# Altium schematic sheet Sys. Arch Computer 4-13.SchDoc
size 762 x 381 mm; SheetNumber: 1; SheetTotal: 1
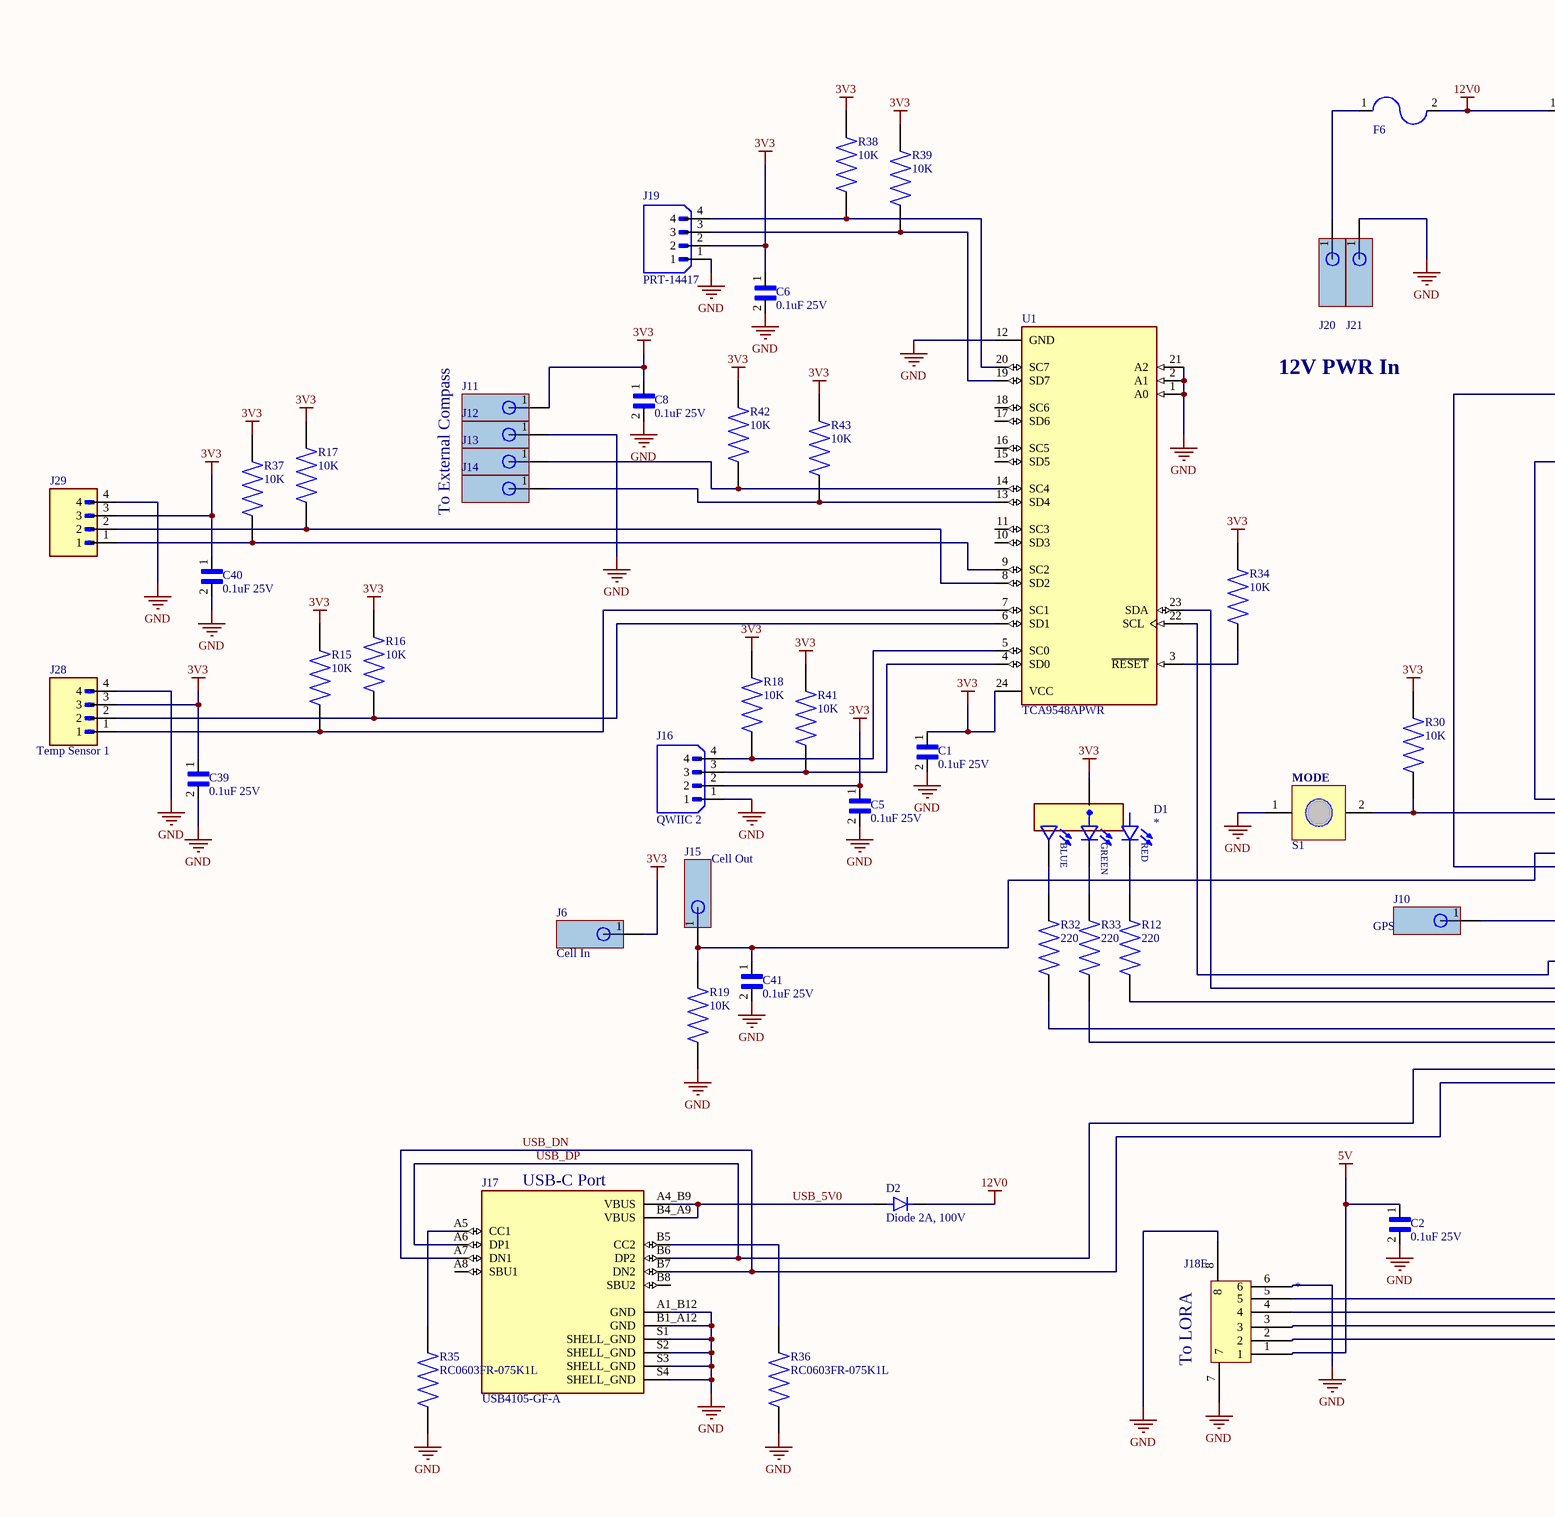
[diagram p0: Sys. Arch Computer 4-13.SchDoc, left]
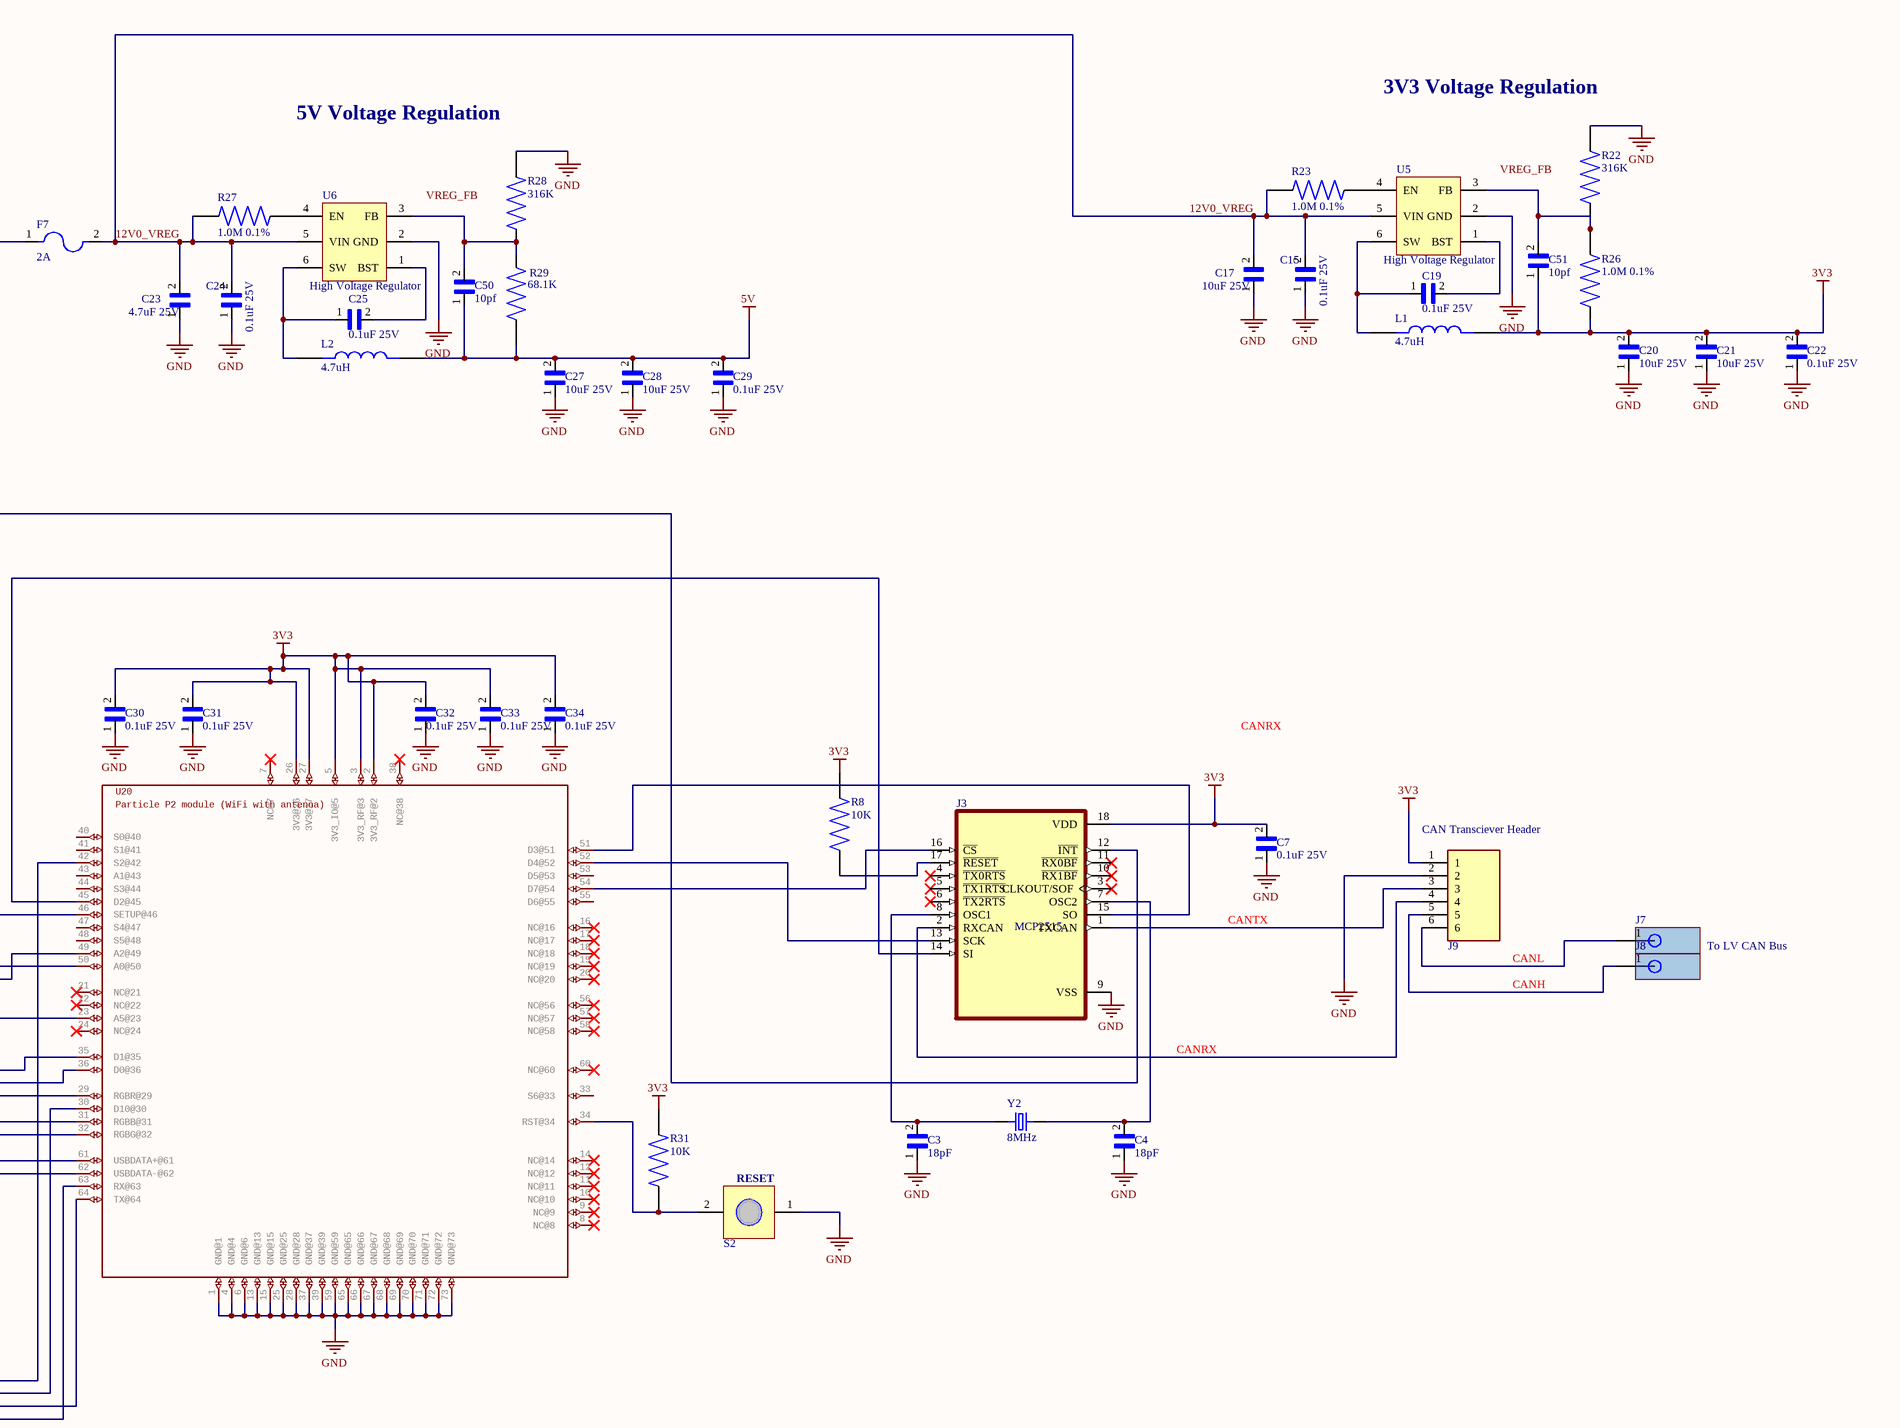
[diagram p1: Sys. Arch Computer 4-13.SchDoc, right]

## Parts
C1  0.1uF 25V  [CAPC1608X90N - duplicate]
C2  0.1uF 25V  [CAPC1608X90N - duplicate]
C3  18pF  [CAPC1608X90N - duplicate1]
C4  18pF  [CAPC1608X90N - duplicate1]
C5  0.1uF 25V  [CAPC1608X90N - duplicate]
C6  0.1uF 25V  [CAPC1608X90N - duplicate]
C7  0.1uF 25V  [CAPC1608X90N - duplicate]
C8  0.1uF 25V  [CAPC1608X90N - duplicate]
C15  0.1uF 25V  [CAPC1608X90N - duplicate]
C17  10uF 25V  [CAPC1608X90N - duplicate1]
C19  0.1uF 25V  [CAPC1608X90N - duplicate]
C20  10uF 25V  [CAPC1608X90N - duplicate1]
C21  10uF 25V  [CAPC1608X90N - duplicate1]
C22  0.1uF 25V  [CAPC1608X90N - duplicate]
C23  4.7uF 25V  [CAPC1608X90N - duplicate1]
C24  0.1uF 25V  [CAPC1608X90N - duplicate]
C25  0.1uF 25V  [CAPC1608X90N - duplicate]
C27  10uF 25V  [CAPC1608X90N - duplicate1]
C28  10uF 25V  [CAPC1608X90N - duplicate1]
C29  0.1uF 25V  [CAPC1608X90N - duplicate]
C30  0.1uF 25V  [CAPC1608X90N - duplicate]
C31  0.1uF 25V  [CAPC1608X90N - duplicate]
C32  0.1uF 25V  [CAPC1608X90N - duplicate]
C33  0.1uF 25V  [CAPC1608X90N - duplicate]
C34  0.1uF 25V  [CAPC1608X90N - duplicate]
C39  0.1uF 25V  [CAPC1608X90N - duplicate]
C40  0.1uF 25V  [CAPC1608X90N - duplicate]
C41  0.1uF 25V  [CAPC1608X90N - duplicate]
C50  10pf  [CAPC1005X55N]
C51  10pf  [CAPC1005X55N]
D1  *  [LED_CLMVC-FKA-CL1D1L71BB7C3C3]
D2  Diode 2A, 100V  [SODFL5226X100N]
F6  MiniAutomotiveFuseHolder  [MiniBladeFuseHolder]  (value not drawn)
F7  2A  [FUSC1608X56N]
J3  MCP2515  [SOIC127P1030X265-18N]
J6  Cell In  [AndersonVerticalMount]
J7  Anderson connector symbol  [AndersonVerticalMount]  (value not drawn)
J8  Anderson connector symbol  [AndersonVerticalMount]  (value not drawn)
J9  0.1 Inch Header 6 Position  [TE_535541-4]  (value not drawn)
J10  GPS  [AndersonVerticalMount]
J11  (no value)  [AndersonVerticalMount]
J12  (no value)  [AndersonVerticalMount]
J13  (no value)  [AndersonVerticalMount]
J14  (no value)  [AndersonVerticalMount]
J15  Cell Out  [AndersonVerticalMount]
J16  QWIIC 2  [SPARKFUN_PRT-14417]
J17  USB4105-GF-A  [GCT_USB4105-GF-A]
J18  *  [ZH1.5-6P-WT]  (part E of 5)
J19  PRT-14417  [SPARKFUN_PRT-14417]
J20  Anderson connector symbol  [EdgeMountAnderson]  (value not drawn)
J21  Anderson connector symbol  [EdgeMountAnderson]  (value not drawn)
J28  (no value)  [SEEED_110990037]
J29  (no value)  [SEEED_110990037]
L1  4.7uH  [IND_NR6028T4R7M]
L2  4.7uH  [IND_NR6028T4R7M]
R8  10K  [RESC1608X55N]
R12  220  [RESC2012X65N]
R15  10K  [RESC1608X55N]
R16  10K  [RESC1608X55N]
R17  10K  [RESC1608X55N]
R18  10K  [RESC1608X55N]
R19  10K  [RESC1608X55N]
R22  316K  [RESC1608X55N]
R23  1.0M 0.1%  [RES_ERJ-PB6B1004V]
R26  1.0M 0.1%  [RES_ERJ-PB6B1004V]
R27  1.0M 0.1%  [RES_ERJ-PB6B1004V]
R28  316K  [RESC1608X55N]
R29  68.1K  [RES_ERJ-PB6B1004V]
R30  10K  [RESC1608X55N]
R31  10K  [RESC1608X55N]
R32  220  [RESC2012X65N]
R33  220  [RESC2012X65N]
R34  10K  [RESC1608X55N]
R35  RC0603FR-075K1L  [RESC1608X55N]
R36  RC0603FR-075K1L  [RESC1608X55N]
R37  10K  [RESC1608X55N]
R38  10K  [RESC1608X55N]
R39  10K  [RESC1608X55N]
R41  10K  [RESC1608X55N]
R42  10K  [RESC1608X55N]
R43  10K  [RESC1608X55N]
S1  Multi-style tactile button  [MultiButton]  (value not drawn)
S2  Multi-style tactile button  [MultiButton]  (value not drawn)
U1  TCA9548APWR  [SOP65P640X120-24N]
U5  High Voltage Regulator  [MP2460GJ-Z]
U6  High Voltage Regulator  [MP2460GJ-Z]
U20  Particle P2 module (WiFi with antenna)  [P2]
Y2  8MHz  [XTAL_ECS-80-18-5PX-TR]

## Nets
3V3: C1.1 C5.1 C6.1 C7.2 C8.1 C20.2 C21.2 C22.2 C30.2 C31.2 C32.2 C33.2 C34.2 C39.1 C40.1 C51.1 D1.1 J3.18(VDD) J6.1 J9.1 J11.1 J16.2 J19.2 J28.3 J29.3 L1.2 R8.2 R15.2 R16.2 R17.2 R18.2 R26.1 R30.2 R31.2 R34.2 R37.2 R38.2 R39.2 R41.2 R42.2 R43.2 U1.24(VCC) U20.2(3V3_RF@2) U20.3(3V3_RF@3) U20.5(3V3_IO@5) U20.26(3V3@26) U20.27(3V3@27)
5V: C2.1 C27.2 C28.2 C29.2 C50.1 J18.1 L2.2 R29.1
12V0: D2.1(K) F6.2 F7.1
GND: C1.2 C2.2 C3.1 C4.1 C5.2 C6.2 C7.1 C8.2 C15.1 C17.1 C20.1 C21.1 C22.1 C23.1 C24.1 C27.1 C28.1 C29.1 C30.1 C31.1 C32.1 C33.1 C34.1 C39.2 C40.2 C41.2 J3.9(VSS) J9.2 J12.1 J16.1 J17.A1_B12(GND) J17.B1_A12(GND) J17.S1(SHELL_GND) J17.S2(SHELL_GND) J17.S3(SHELL_GND) J17.S4(SHELL_GND) J18.6 J18.7 J18.8 J19.1 J21.1 J28.4 J29.4 R19.1 R22.2 R28.2 R35.1 R36.1 S1.1 S2.1 U1.1(A0) U1.2(A1) U1.12(GND) U1.21(A2) U5.2(GND) U6.2(GND) U20.1(GND@1) U20.4(GND@4) U20.6(GND@6) U20.13(GND@13) U20.15(GND@15) U20.25(GND@25) U20.28(GND@28) U20.37(GND@37) U20.39(GND@39) U20.59(GND@59) U20.65(GND@65) U20.66(GND@66) U20.67(GND@67) U20.68(GND@68) U20.69(GND@69) U20.70(GND@70) U20.71(GND@71) U20.72(GND@72) U20.73(GND@73)
12V0_VREG: C15.2 C17.2 C23.2 C24.2 F7.2 R23.2 R27.2 U5.5(VIN) U6.5(VIN)
USB_5V0: D2.2(A) J17.A4_B9(VBUS) J17.B4_A9(VBUS)
USB_DN: J17.A7(DN1) J17.B7(DN2) U20.62(USBDATA-@62)
USB_DP: J17.A6(DP1) J17.B6(DP2) U20.61(USBDATA+@61)
NetC3_2: C3.2 J3.8(OSC1) Y2.1
NetC4_2: C4.2 J3.7(OSC2) Y2.2
NetC19_1: C19.1 L1.1 U5.6(SW)
NetC19_2: C19.2 U5.1(BST)
NetC25_1: C25.1 L2.1 U6.6(SW)
NetC25_2: C25.2 U6.1(BST)
NetC41_1: C41.1 J15.1 R19.2 U20.49(A2@49)
NetC50_2: C50.2 R28.1 R29.2 U6.3(FB)
NetC51_2: C51.2 R22.1 R26.2 U5.3(FB)
NetD1_2: D1.2 R32.2
NetD1_3: D1.3 R33.1
NetD1_4: D1.4 R12.1
NetF6_1: F6.1 J20.1
NetJ3_1: J3.1(TXCAN) J9.3
NetJ3_2: J3.2(RXCAN) J9.4
NetJ3_12: J3.12(~{INT}) U20.50(A0@50)
NetJ3_13: J3.13(SCK) U20.52(D4@52)
NetJ3_14: J3.14(SI) U20.45(D2@45)
NetJ3_15: J3.15(SO) U20.51(D3@51)
NetJ3_16: J3.16(~{CS}) U20.54(D7@54)
NetJ3_17: J3.17(~{RESET}) R8.1
NetJ7_1: J7.1 J9.6
NetJ8_1: J8.1 J9.5
NetJ10_1: J10.1 U20.23(A5@23)
NetJ13_1: J13.1 R42.1 U1.14(SC4)
NetJ14_1: J14.1 R43.1 U1.13(SD4)
NetJ16_3: J16.3 R41.1 U1.4(SD0)
NetJ16_4: J16.4 R18.1 U1.5(SC0)
NetJ17_A5: J17.A5(CC1) R35.2
NetJ17_B5: J17.B5(CC2) R36.2
NetJ18_2: J18.2 U20.63(RX@63)
NetJ18_3: J18.3 U20.64(TX@64)
NetJ18_4: J18.4 U20.30(D10@30)
NetJ18_5: J18.5 U20.42(S2@42)
NetJ19_3: J19.3 R39.1 U1.19(SD7)
NetJ19_4: J19.4 R38.1 U1.20(SC7)
NetJ28_1: J28.1 R15.1 U1.7(SC1)
NetJ28_2: J28.2 R16.1 U1.6(SD1)
NetJ29_1: J29.1 R37.1 U1.9(SC2)
NetJ29_2: J29.2 R17.1 U1.8(SD2)
NetR12_2: R12.2 U20.29(RGBR@29)
NetR23_1: R23.1 U5.4(EN)
NetR27_1: R27.1 U6.4(EN)
NetR30_1: R30.1 S1.2 U20.46(SETUP@46)
NetR31_1: R31.1 S2.2 U20.34(RST@34)
NetR32_1: R32.1 U20.31(RGBB@31)
NetR33_2: R33.2 U20.32(RGBG@32)
NetR34_1: R34.1 U1.3(~{RESET})
NetU1_22: U1.22(SCL) U20.35(D1@35)
NetU1_23: U1.23(SDA) U20.36(D0@36)

Not connected (* = marked no-connect by the designer): J3 3(CLKOUT/SOF)* 4(~{TX0RTS})* 5(~{TX1RTS})* 6(~{TX2RTS})* 10(~{RX1BF})* 11(~{RX0BF})*; J17 A8(SBU1) B8(SBU2); U1 10(SD3) 11(SC3) 15(SD5) 16(SC5) 17(SD6) 18(SC6); U20 7(NC@7)* 8(NC@8)* 9(NC@9)* 10(NC@10)* 11(NC@11)* 12(NC@12)* 14(NC@14)* 16(NC@16)* 17(NC@17)* 18(NC@18)* 19(NC@19)* 20(NC@20)* 21(NC@21)* 22(NC@22)* 24(NC@24)* 33(S6@33) 38(NC@38)* 40(S0@40) 41(S1@41) 43(A1@43) 44(S3@44) 47(S4@47) 48(S5@48) 53(D5@53) 55(D6@55) 56(NC@56)* 57(NC@57)* 58(NC@58)* 60(NC@60)*

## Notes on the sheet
- 5V Voltage Regulation
- 3V3 Voltage Regulation
- 12V PWR In
- To External Compass
- CANRX
- (near J28) Temp Sensor 1
- (near J9) CAN Transciever Header
- (near S1) MODE
- CANTX
- CANL
- CANH
- To LV CAN Bus
- (near S2) RESET
- (near J17) USB-C Port
- (near J18) To LORA
- Labels drawn without touching a wire or pin: VREG_FB

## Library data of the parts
C1 C2 C5-C8 C15 C19 C22 C24 C25 C29-C34 C39-C41 = CL10B104KA8NNNC: 0.1 µF ±10% 25V Ceramic Capacitor 0603; MF: {'manufacturer': u'Samsung Electro-Mechanics'}
C3 C4 = 06035A180JAT4A: 18PF 50V CAPACITOR 5%, 0603; MF: {'manufacturer': u'AVX'}
C17 C20 C21 C23 C27 C28 = CL21A106KAYNNNE: 10uF 25V Cap Ceramic 0805 X5R 10% SMD; MF: {'manufacturer': u'Samsung Electro-Mechanics'}
C50 C51 = GRM1555C1H100JA01D: SMD Capacitor C0G_EIA_ with Capacitance: 10pF Tol. 5%. Rated Voltage: 50Vdc; MF: Murata
D1 = CLMVC-FKA-CL1D1L71BB7C3C3: Red, Green, Blue (RGB) 622nm Red, 530nm Green, 470nm Blue LED Indication - Discrete 2V Red, 3V Green, 3V Blue 4-SMD, J-Lead; MF: {'manufacturer': u'Cree Inc.'}
D2 = SS210ALH: Diode 2A 100V, Generic; MF: {'manufacturer': u'Taiwan Semiconductor'}
F6 = MiniBladeFuseHolder: Blade Fuse Holder Automotive Mini
F7 = C2Q-2: 2A 32V Board Mount Fuse; MF: {'manufacturer': u'Bel Fuse'}
J3 = MCP2515-I/SO: CANbus Controller CAN 2.0 SPI Interface 18-SOIC; MF: {'manufacturer': u'Microchip'}
J6-J8 J10-J15 = AndersonConnVert: Anderson Connector, Single. Vertical Mount
J9 = 535541-4: MF: {'manufacturer': u'TE Connectivity'}
J16 J19 = PRT-14417: QWIIC JST CONNECTOR - SMD 4-PIN; MF: SparkFun Electronics
J17 = USB4105-GF-A: USB-C (USB TYPE-C) USB 2.0 Receptacle Connector 24 (16+8 Dummy) Position Surface Mount, Right Angle; Through Hole; MF: {'manufacturer': u'GCT'}
J18 = Component_1
J20 J21 = AndersonConn
J28 J29 = 110990037: GROVE 2MM 4PIN R/A CONN 10PACK; MF: Seeed Technology
L1 L2 = NR6028T4R7M: Inductor Power Shielded Wirewound 4.7uH 20% 100KHz Ferrite 3A 40.3mOhm DCR 2424 T/R; MF: {'manufacturer': u'Taiyo Yuden'}
R8 R30 R31 = CRGCQ0603J10K: 10K Resistor 0603 5%; MF: {'manufacturer': u'TE Connectivity'}
R12 R32 R33 = CRGCQ0805J220R: 220 Ohm Resistor 0805 5%; MF: {'manufacturer': u'TE Connectivity'}
R15-R19 R34 R37-R39 R41-R43 = CRGCQ0603J10K: Fixed Resistor CRGCQ 0603 10K 5%; MF: TE Connectivity
R22 R28 = RC0603FR-07316KL: 316 kOhms 0603 0.1 W  1% SMT Thick Film Chip Resistor; MF: {'manufacturer': u'Yageo'}
R23 R26 R27 R29 = ERJ-PB6B1004V: 1 MOhms ±0.1% 0.25W, 1/4W Chip Resistor 0805; MF: {'manufacturer': u'Panasonic'}
R35 R36 = RC0603FR-075K1L: 5.10K OHM Resistor 1/10W 1% 0603 SMD; MF: {'manufacturer': u'Yageo'}
S1 S2 = ModularButton: Multi-style tactile button, compatible with many common buttons
U1 = TCA9548APWR: 8-channel 1.65- to 5.5-V I2C/SMBus switch with reset & voltage translation; MF: Texas Instruments
U5 U6 = MP2460GJ-Z: Buck Switching Regulator IC Positive Adjustable 0.8V 1 Output 600mA SOT-23-6 Thin, TSOT-23-6
U20 = P2: GateName_1: G$1
Y2 = ECS-80-18-5PX-TR: CRYSTAL SMD 8MHz; MF: {'manufacturer': u'ECS Inc.'}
